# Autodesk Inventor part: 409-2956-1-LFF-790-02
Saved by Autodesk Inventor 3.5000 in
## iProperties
Created: 2010-09
Part Number: 409-2956-1-LFF-790-02
Cost Center: 0 lbmass
Material: A304 STAINLESS STEEL
Document SubType Name: Sheet Metal
Designer: S. Boerckel
Authority: 0 in^3
Mass: 1027.78 g
Surface Area: 319.706 cm^2
Volume: 127.201 cm^3
Density: 8.08 g/cm^3
Flat Pattern Width: 8.89 cm
Flat Pattern Length: 15.24 cm
Flat Pattern Area: 135.484 cm^2
Sheet Metal Rule: 3/8"Thk
Sheet Metal Width: 6.0000 in
Sheet Metal Length: 21.0000 in^2
Description: BASE PLATE
User Status: BURN
SaveDate: 2008-01-15
SaveTime: 10:24
FileName: Sheet Metal
Wide: =<Flat Pattern Width>cm
Length: =<Flat Pattern Length>cm
Thickness: 0.3750 in
SMR: =<Sheet Metal Rule> - <Material>
Author: S. Boerckel
Revision Number: 0
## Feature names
1. Hole1
2. Plate1
